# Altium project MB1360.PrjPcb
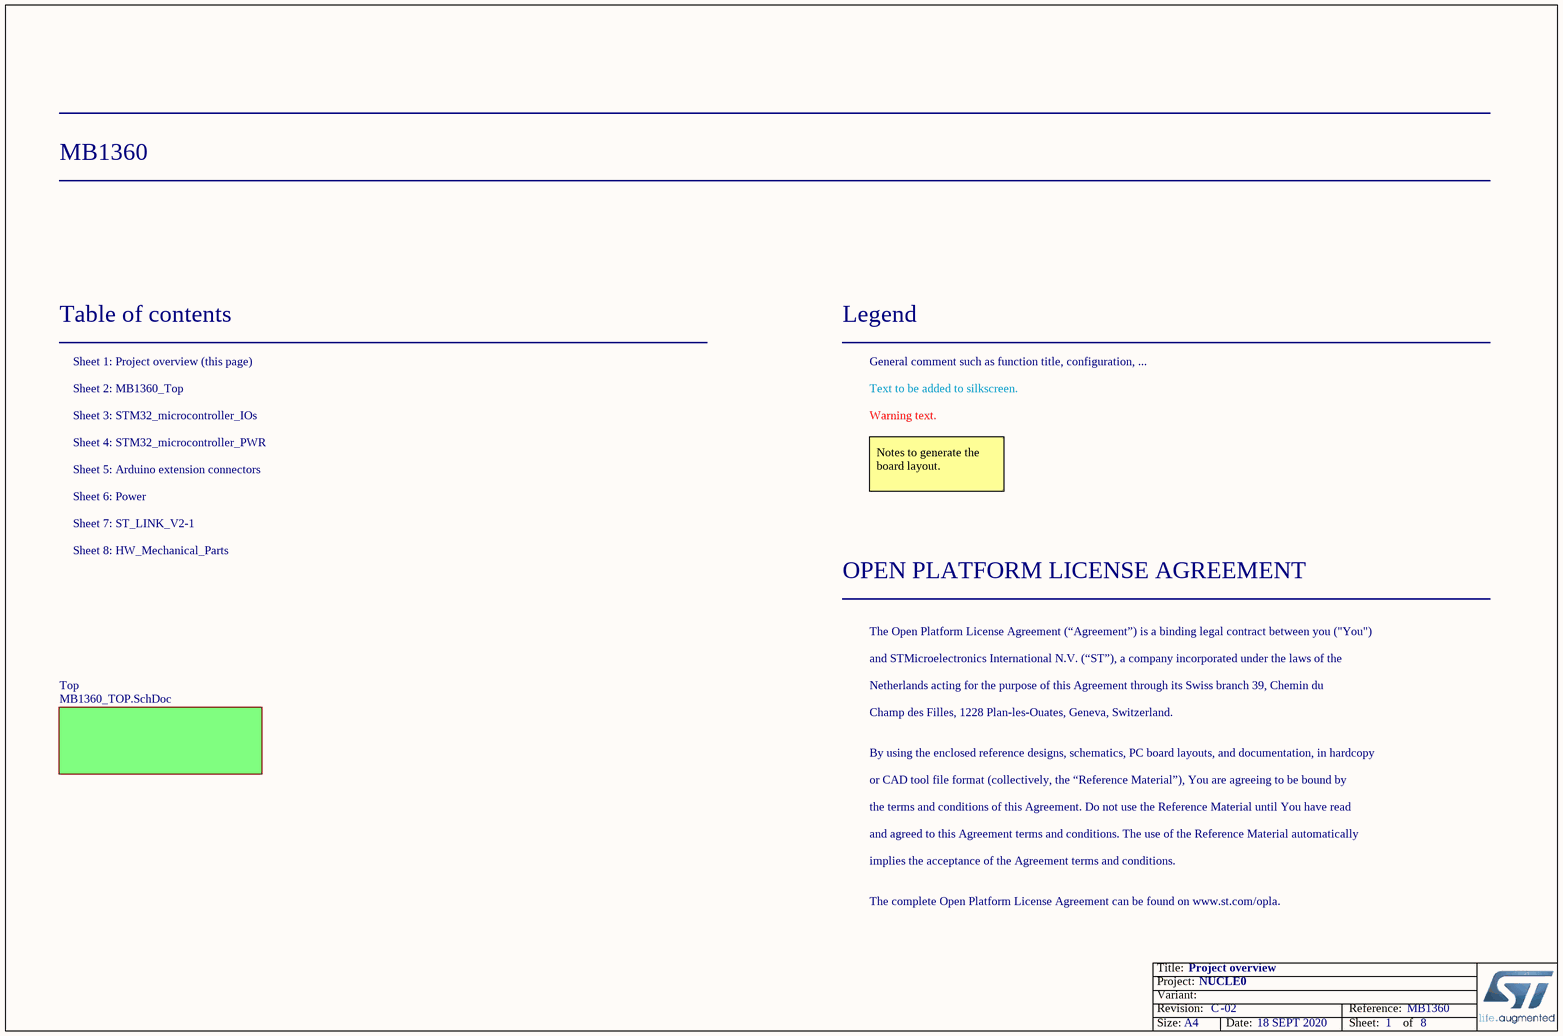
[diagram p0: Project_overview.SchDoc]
Board_Reference: MB1360; Board_PCB_Revision: C; Board_Name: NUCLE0; Board_Document_Date: 18 SEPT 2020; Board_Assembly_Revision: 02
8 sheets, 150 parts. Net scope: flat (ports and power ports of the same name join across sheets).
Board file: MB1360.PcbDoc
Sheets:
  Project_overview.SchDoc
    Top = MB1360_TOP.SchDoc
      ST_LINK_V2-1 = ST_LINK_V2-1.SchDoc
      Connectors = Arduino_extension_connectors.SchDoc
      MCU = STM32_microcontroller_IOs.SchDoc
      Power = Power.SchDoc
      STM32_microcontroller_power = STM32_microcontroller_power.SchDoc
      HW_Mechanical_Parts = HW_Mechanical_Parts.SchDoc

## Sheet Project_overview.SchDoc: Project overview
size A4; Date: Not used; ApprovedBy: Not used; CheckedBy: Not used; Author: Not used; CompanyName: STMicroelectronics; DrawnBy: Not used; Engineer: Not used; Organization: Not used; Address1: Not used; Address2: Not used; Address3: Not used; Address4: Not used; DocumentNumber: 1; Revision: Not used; SheetNumber: 1; SheetTotal: 8

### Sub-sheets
Top = MB1360_TOP.SchDoc: no entries

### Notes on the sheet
- Table of contents
- Sheet 1: Project overview (this page)
- Legend
- General comment such as function title, configuration, ...
- Sheet 2: MB1360_Top
- Sheet 4: STM32_microcontroller_PWR
- Sheet 3: STM32_microcontroller_IOs
- Text to be added to silkscreen.
- Warning text.
- Sheet 6: Power
- Sheet 5: Arduino extension connectors
- Notes to generate the board layout.
- Sheet 7: ST_LINK_V2-1
- Sheet 8: HW_Mechanical_Parts
- OPEN PLATFORM LICENSE AGREEMENT
- The Open Platform License Agreement (“Agreement”) is a binding legal contract between you ("You")
- and STMicroelectronics International N.V. (“ST”), a company incorporated under the laws of the
- Netherlands acting for the purpose of this Agreement through its Swiss branch 39, Chemin du
- Champ des Filles, 1228 Plan-les-Ouates, Geneva, Switzerland.
- By using the enclosed reference designs, schematics, PC board layouts, and documentation, in hardcopy
- or CAD tool file format (collectively, the “Reference Material”), You are agreeing to be bound by
- the terms and conditions of this Agreement. Do not use the Reference Material until You have read
- and agreed to this Agreement terms and conditions. The use of the Reference Material automatically
- implies the acceptance of the Agreement terms and conditions.
- The complete Open Platform License Agreement can be found on www.st.com/opla.

## Sheet MB1360_TOP.SchDoc: TOP
size A4; CompanyName: STMicroelectronics; Organization: Microcontrollers Division; SheetNumber: 2; SheetTotal: 8
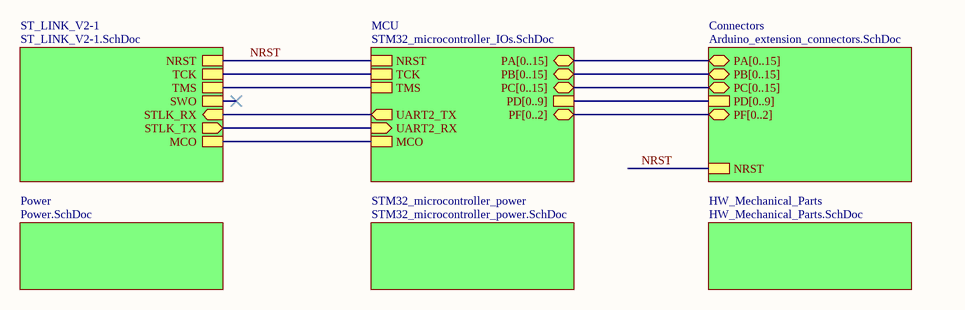
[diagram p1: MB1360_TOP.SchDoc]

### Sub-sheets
Connectors = Arduino_extension_connectors.SchDoc: PA[0..15] (bidir), PB[0..15] (bidir), PC[0..15] (bidir), NRST, PD[0..9], PF[0..2] (bidir)
HW_Mechanical_Parts = HW_Mechanical_Parts.SchDoc: no entries
MCU = STM32_microcontroller_IOs.SchDoc: NRST, MCO, UART2_RX (in), UART2_TX (out), PA[0..15] (bidir), PB[0..15] (bidir), PC[0..15] (bidir), TCK, TMS, PD[0..9], PF[0..2] (bidir)
Power = Power.SchDoc: no entries
ST_LINK_V2-1 = ST_LINK_V2-1.SchDoc: TMS, TCK, MCO, NRST, STLK_RX (in), STLK_TX (out), SWO
STM32_microcontroller_power = STM32_microcontroller_power.SchDoc: no entries

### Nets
NRST: sheet ST_LINK_V2-1/NRST, sheet Connectors/NRST, sheet MCU/NRST
(unnamed): sheet ST_LINK_V2-1/TMS, sheet MCU/TMS
(unnamed): sheet ST_LINK_V2-1/TCK, sheet MCU/TCK  [a separate net that carries the same name]
(unnamed): sheet ST_LINK_V2-1/MCO, sheet MCU/MCO  [a separate net that carries the same name]
(unnamed): sheet ST_LINK_V2-1/STLK_RX, sheet MCU/UART2_TX  [a separate net that carries the same name]
(unnamed): sheet ST_LINK_V2-1/STLK_TX, sheet MCU/UART2_RX  [a separate net that carries the same name]

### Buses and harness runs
bus sheet Connectors/PA[0..15] = sheet MCU/PA[0..15]
bus sheet Connectors/PB[0..15] = sheet MCU/PB[0..15]
bus sheet Connectors/PC[0..15] = sheet MCU/PC[0..15]
bus sheet Connectors/PD[0..9] = sheet MCU/PD[0..9]
bus sheet Connectors/PF[0..2] = sheet MCU/PF[0..2]

## Sheet ST_LINK_V2-1.SchDoc: ST_LINK_V2-1
size A4; CompanyName: STMicroelectronics; Organization: Microcontrollers Division; SheetNumber: 7; SheetTotal: 8
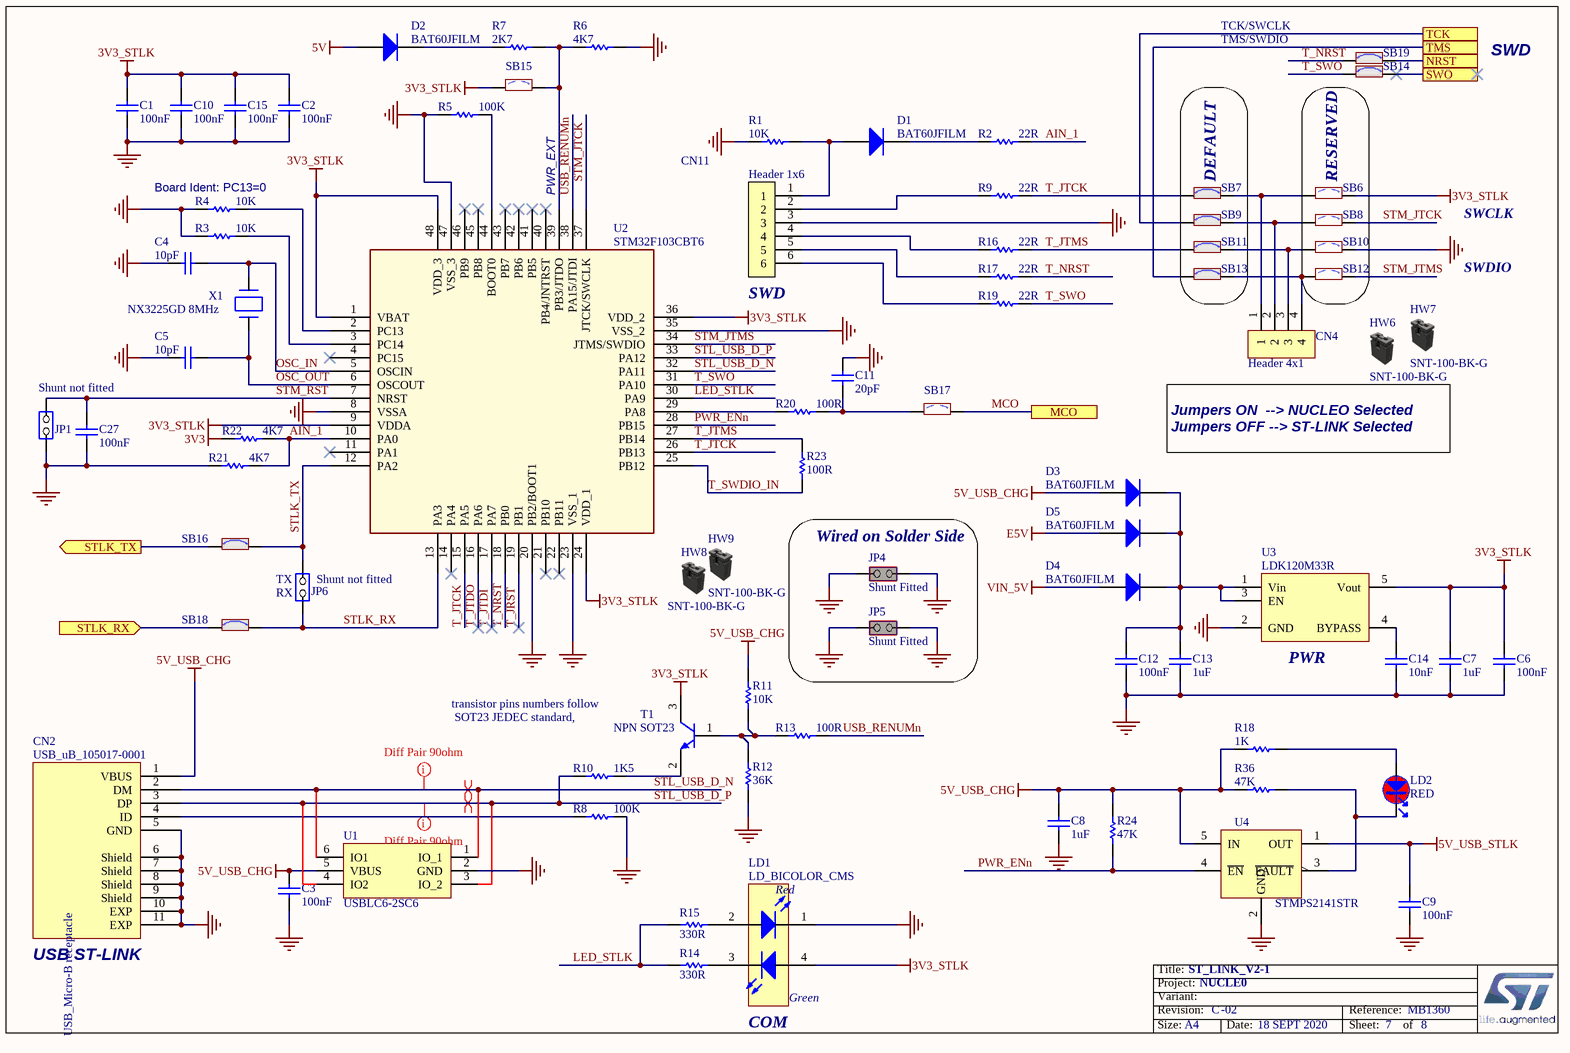
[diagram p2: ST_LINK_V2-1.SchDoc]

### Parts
C1  value 100nF  [C0603]  (hidden comment: Capacitor)
C2  value 100nF  [C0603]  (hidden comment: Capacitor)
C3  value 100nF  [C0603]  (hidden comment: Capacitor)
C4  value 10pF  [C0603]  (hidden comment: Capacitor)
C5  value 10pF  [C0603]  (hidden comment: Capacitor)
C6  value 100nF  [C0603]  (hidden comment: Capacitor)
C7  value 1uF  [C0603]  (hidden comment: Capacitor)
C8  value 1uF  [C0603]  (hidden comment: Capacitor)
C9  value 100nF  [C0603]  (hidden comment: Capacitor)
C10  value 100nF  [C0603]  (hidden comment: Capacitor)
C11  value 20pF  [C0603]  (hidden comment: Capacitor)
C12  value 100nF  [C0603]  (hidden comment: Capacitor)
C13  value 1uF  [C0603]  (hidden comment: Capacitor)
C14  value 10nF  [C0603]  (hidden comment: Capacitor)
C15  value 100nF  [C0603]  (hidden comment: Capacitor)
C27  value 100nF  [C0603]  (hidden comment: Capacitor)
CN2  value USB_uB_105017-0001  [CON_USBMICROB_MOLEX_105017-0001_H2P90]  (hidden comment: USB_uB_105017.0001)
CN4  Header 4x1  [CON_988-JIUBABA_PHFS25-11-04-G0B115-T-1]
CN11  value Header 1x6  [CON_988-JIUBABA_PHFS25-11-06-G0B115-T-1]  (hidden comment: Header 6x1)
D1  BAT60JFILM  [DIO_SOD323]
D2  BAT60JFILM  [DIO_SOD323]
D3  BAT60JFILM  [DIO_SOD323]
D4  BAT60JFILM  [DIO_SOD323]
D5  BAT60JFILM  [DIO_SOD323]
HW6  value SNT-100-BK-G  (hidden comment: Shunt Black 2.54mm)  (mechanical)
HW7  value SNT-100-BK-G  (hidden comment: Shunt Black 2.54mm)  (mechanical)
HW8  value SNT-100-BK-G  (hidden comment: Shunt Black 2.54mm)  (mechanical)
HW9  value SNT-100-BK-G  (hidden comment: Shunt Black 2.54mm)  (mechanical)
JP1  value Shunt not fitted  [CON_SAMTEC_TSW-102-07-G-S]  (hidden comment: Jumper_Header 2x1)
JP4  value Shunt Fitted  [CON_SAMTEC_TSW-102-07-G-S]  (hidden comment: Jumper_Header 2x1 Fitted)
JP5  value Shunt Fitted  [CON_SAMTEC_TSW-102-07-G-S]  (hidden comment: Jumper_Header 2x1 Fitted)
JP6  value Shunt not fitted  [CON_SAMTEC_TSW-102-07-G-S]  (hidden comment: Jumper_Header 2x1)
LD1  LD_BICOLOR_CMS  [LED_BI-GR_HSMF-A201-A00J1]
LD2  value RED  [LED_0603_RED]  (hidden comment: LED_red)
R1  value 10K  [R0603]  (hidden comment: Resistor)
R2  value 22R  [R0603]  (hidden comment: Resistor)
R3  value 10K  [R0603]  (hidden comment: Resistor)
R4  value 10K  [R0603]  (hidden comment: Resistor)
R5  value 100K  [R0603]  (hidden comment: Resistor)
R6  value 4K7  [R0603]  (hidden comment: Resistor)
R7  value 2K7  [R0603]  (hidden comment: Resistor)
R8  value 100K  [R0603]  (hidden comment: Resistor)
R9  value 22R  [R0603]  (hidden comment: Resistor)
R10  value 1K5  [R0603]  (hidden comment: Resistor)
R11  value 10K  [R0603]  (hidden comment: Resistor)
R12  value 36K  [R0603]  (hidden comment: Resistor)
R13  value 100R  [R0603]  (hidden comment: Resistor)
R14  value 330R  [R0603]  (hidden comment: Resistor)
R15  value 330R  [R0603]  (hidden comment: Resistor)
R16  value 22R  [R0603]  (hidden comment: Resistor)
R17  value 22R  [R0603]  (hidden comment: Resistor)
R18  value 1K  [R0603]  (hidden comment: Resistor)
R19  value 22R  [R0603]  (hidden comment: Resistor)
R20  value 100R  [R0603]  (hidden comment: Resistor)
R21  value 4K7  [R0603]  (hidden comment: Resistor)
R22  value 4K7  [R0603]  (hidden comment: Resistor)
R23  value 100R  [R0603]  (hidden comment: Resistor)
R24  value 47K  [R0603]  (hidden comment: Resistor)
R36  value 47K  [R0603]  (hidden comment: Resistor)
SB6  SB_OFF  [SOLDER-BRIDGE_R0603-0R]  (value not drawn)
SB7  SB_ON  [SOLDER-BRIDGE_R0603-0R]  (value not drawn)
SB8  SB_OFF  [SOLDER-BRIDGE_R0603-0R]  (value not drawn)
SB9  SB_ON  [SOLDER-BRIDGE_R0603-0R]  (value not drawn)
SB10  SB_OFF  [SOLDER-BRIDGE_R0603-0R]  (value not drawn)
SB11  SB_ON  [SOLDER-BRIDGE_R0603-0R]  (value not drawn)
SB12  SB_OFF  [SOLDER-BRIDGE_R0603-0R]  (value not drawn)
SB13  SB_ON  [SOLDER-BRIDGE_R0603-0R]  (value not drawn)
SB14  SB_ON  [SOLDER-BRIDGE_R0603-0R]  (value not drawn)
SB15  SB_OFF  [SOLDER-BRIDGE_R0603-0R]  (value not drawn)
SB16  SB_ON  [SOLDER-BRIDGE_R0603-0R]  (value not drawn)
SB17  SB_OFF  [SOLDER-BRIDGE_R0603-0R]  (value not drawn)
SB18  SB_ON  [SOLDER-BRIDGE_R0603-0R]  (value not drawn)
SB19  SB_ON  [SOLDER-BRIDGE_R0603-0R]  (value not drawn)
T1  value NPN SOT23  [NPN_SOT23]  (hidden comment: 9013-SOT23)
U1  USBLC6-2SC6  [ESD_SOT23-6L]
U2  STM32F103CBT6  [ICC_LQFP48_7X7_P050]
U3  LDK120M33R  [REG_SOT23-5L]
U4  STMPS2141STR  [MOS_SOT23-5L]
X1  value NX3225GD 8MHz  [CRY_NX3225GD_2P]  (hidden comment: XTAL_2_PINS)

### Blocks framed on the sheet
DEFAULT: SB7 SB9 SB11 SB13
RESERVED: SB6 SB8 SB10 SB12
Wired on Solder Side: JP4 JP5

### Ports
MCO, NRST, STLK_RX (in), STLK_TX (out), SWO, TCK, TMS

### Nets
3V3: R22.1
3V3_STLK: C1.2 C2.2 C6.2 C7.2 C10.2 C15.2 LD1.4(YellowGreen_anode) SB6.2 SB15.1 T1.3(C) U2.1(VBAT) U2.9(VDDA) U2.24(VDD_1) U2.36(VDD_2) U2.48(VDD_3) U3.5(Vout)
5V: D2.1(A)
5V_USB_CHG: C3.2 C8.1 CN2.1(VBUS) D3.1(A) R11.2 R18.2 R24.2 R36.2 U1.5(VBUS) U4.5(IN)
5V_USB_STLK: C9.2 U4.1(OUT)
E5V: D5.1(A)
GND: C1.1 C2.1 C3.1 C4.1 C5.1 C6.1 C7.1 C8.2 C9.1 C10.1 C11.2 C12.1 C13.1 C14.1 C15.1 C27.2 CN2.5(GND) CN2.6(Shield) CN2.7(Shield) CN2.8(Shield) CN2.9(Shield) CN2.10(EXP) CN2.11(EXP) CN11.3 JP1.2(NO) JP4.1(COMMON) JP4.2(NO) JP5.1(COMMON) JP5.2(NO) LD1.1(RED_cathode) R1.2 R3.1 R4.1 R5.1 R6.2 R8.2 R12.1 R21.1 SB10.2 U1.2(GND) U2.8(VSSA) U2.20(PB2/BOOT1) U2.23(VSS_1) U2.35(VSS_2) U2.47(VSS_3) U3.2(GND) U4.2(GND)
VIN_5V: D4.1(A)
AIN_1: R2.2 R21.2 R22.2 U2.10(PA0)
LED_STLK: R14.1 R15.1 U2.30(PA9)
MCO: SB17.2 ; port MCO
NRST: SB19.2 ; port NRST
OSC_IN: C4.2 U2.5(OSCIN) X1.2(X2)
OSC_OUT: C5.2 U2.6(OSCOUT) X1.1(X1)
PA13: SB13.1 ; port TMS
PA14: SB9.1 ; port TCK
PWR_ENn: R24.1 U2.28(PB15) U4.4(~{EN})
STL_USB_D_N: CN2.2(DM) U1.1(IO_1) U1.6(IO1) U2.32(PA11)
STL_USB_D_P: CN2.3(DP) R10.1 U1.3(IO_2) U1.4(IO2) U2.33(PA12)
STLK_RX: JP6.1(COMMON) SB18.2 U2.13(PA3)
STLK_TX: JP6.2(NO) SB16.2 U2.12(PA2)
STM_JTCK: SB8.2 U2.37(JTCK/SWCLK)
STM_JTMS: SB12.2 U2.34(JTMS/SWDIO)
STM_RST: C27.1 JP1.1(COMMON) U2.7(NRST)
T_JRST: U2.19(PB1)
T_JTCK: R9.2 SB7.1 U2.15(PA5) U2.26(PB13)
T_JTDI: U2.17(PA7)
T_JTDO: U2.16(PA6)
T_JTMS: R16.2 R23.2 SB11.1 U2.27(PB14)
T_NRST: R17.2 SB19.1 U2.18(PB0)
T_SWDIO_IN: R23.1 U2.25(PB12)
T_SWO: R19.2 SB14.1 U2.31(PA10)
USB_RENUMn: R13.2 U2.38(PA15/JTDI)
NetC11_1: C11.1 R20.2 SB17.1
NetC12_2: C12.2 C13.2 D3.2(K) D4.2(K) D5.2(K) U3.1(Vin) U3.3(EN)
NetC14_2: C14.2 U3.4(BYPASS)
NetCN2_4: CN2.4(ID) R8.1
NetCN4_1: CN4.1 SB6.1 SB7.2
NetCN4_2: CN4.2 SB8.1 SB9.2
NetCN4_3: CN4.3 SB10.1 SB11.2
NetCN4_4: CN4.4 SB12.1 SB13.2
NetCN11_1: CN11.1 D1.1(A) R1.1
NetCN11_2: CN11.2 R9.1
NetCN11_4: CN11.4 R16.1
NetCN11_5: CN11.5 R17.1
NetCN11_6: CN11.6 R19.1
NetD1_2: D1.2(K) R2.1
NetD2_2: D2.2(K) R7.1
NetLD1_2: LD1.2(Red_anode) R15.2
NetLD1_3: LD1.3(YellowGreen_cathode) R14.2
NetLD2_1: LD2.1 R18.1
NetLD2_2: LD2.2 R36.1 U4.3(~{FAULT})
NetR3_2: R3.2 U2.3(PC14)
NetR4_2: R4.2 U2.2(PC13)
NetR5_2: R5.2 U2.44(BOOT0)
NetR6_1: R6.1 R7.2 SB15.2 U2.39(PB3/JTDO)
NetR10_2: R10.2 T1.2(E)
NetR11_1: R11.1 R12.2 R13.1 T1.1(B)
NetR20_1: R20.1 U2.29(PA8)
NetSB14_2: SB14.2 ; port SWO
NetSB16_1: SB16.1 ; port STLK_TX
NetSB18_1: SB18.1 ; port STLK_RX

Not connected (* = marked no-connect by the designer): U2 4(PC15)* 11(PA1)* 14(PA4)* 21(PB10)* 22(PB11)* 40(PB4/JNTRST)* 41(PB5)* 42(PB6)* 43(PB7)* 45(PB8)* 46(PB9)*

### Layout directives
mark named Diff Pair 90ohm: STL_USB_D_N, STL_USB_D_P
differential pair: STL_USB_D_N, STL_USB_D_P

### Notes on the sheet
- TCK/SWCLK
- TMS/SWDIO
- SWD
- (near R4) Board Ident: PC13=0
- PWR_EXT
- SWCLK
- (near CN11) SWD
- SWDIO
- Jumpers ON  --> NUCLEO Selected
  Jumpers OFF --> ST-LINK Selected
- (near JP6) TX
- (near JP6) RX
- (near U3) PWR
- (near T1) transistor pins numbers follow
  SOT23 JEDEC standard,
- (near CN2) USB ST-LINK
- COM

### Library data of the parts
C1-C3 C6 C9 C10 C12 C15 C27 = MCD-00211: Capacitor, MLCC, 100nF, 16V, X7R, 10%, 0603, T=0,8mm; Manufacturer_Part_Number: CC0603KRX7R7BB104; Manufacturer: YAGEO; ECCN_US: EAR99; ECCN_EU: NEC; Provided_By: SUBCO
C4 C5 = MCD-00637: Capacitor, MLCC, 10pF, 50V, NPO, 5%, 0603, T=0,8mm; Manufacturer_Part_Number: CC0603JRNPO9BN100; Manufacturer: YAGEO; ECCN_US: EAR99; ECCN_EU: NEC; Provided_By: SUBCO
C7 C13 = MCD-00010: Capacitor, MLCC, 1uF, 16V, X5R, 10%, 0603, T=0,8mm; Manufacturer_Part_Number: CC0603KRX5R7BB105; Manufacturer: YAGEO; ECCN_US: EAR99; ECCN_EU: NEC; Provided_By: SUBCO
C8 = MCD-00238: Capacitor, MLCC, 1uF, 6V3, X5R, 10%, 0603, T=0,8mm; Manufacturer_Part_Number: CC0603KRX5R5BB105; Manufacturer: YAGEO; ECCN_US: EAR99; ECCN_EU: NEC; Provided_By: SUBCO
C11 = MCD-00638: Capacitor, MLCC, 20pF, 50V, NPO, 5%, 0603, T=0,8mm; Manufacturer_Part_Number: CC0603JRNPO9BN200; Manufacturer: YAGEO; ECCN_US: EAR99; ECCN_EU: NEC; Provided_By: SUBCO
C14 = MCD-00017: Capacitor, MLCC, 10nF, 50V, X7R, 10%, 0603, T=0.8mm; Manufacturer_Part_Number: CC0603KRX7R9BB103; Manufacturer: YAGEO; ECCN_US: EAR99; ECCN_EU: NEC; Provided_By: SUBCO
CN2 = MCD-00028: USB-MICRO-B, 0.65mm, RA, SMT, Bottom Mount,; Part_Type: Connector; Manufacturer_Part_Number: 1050170001; Manufacturer: MOLEX; Provided_By: SUBCO
CN4 = MCD-00313: Header, 4x1, 2.54mm, VR, TH, Height 6mm/3mm; Part_Type: Connector; Manufacturer_Part_Number: PHFS25-11-04-G0B115-T-1; Manufacturer: JIUBABA; Alternate_Manufacturer_Part_Number: 313104S1411160; Alternate_Manufacturer: LIANYI; Provided_By: SUBCO
CN11 = MCD-00316: Header, 6x1, 2.54mm, VR, TH, Height 6mm/3mm; Part_Type: Connector; Manufacturer_Part_Number: PHFS25-11-06-G0B115-T-1; Manufacturer: JIUBABA; Alternate_Manufacturer_Part_Number: 313106S1411160; Alternate_Manufacturer: LIANYI; Provided_By: SUBCO
D1 D3-D5 = MCD-00034: Part_Type: Diode; Manufacturer: STMICROELECTRONICS; BMS_Part_Number: 9151097; ECCN_US: EAR99; ECCN_EU: NEC; Provided_By: SUBCO with ST control
D2 = MCD-00034: Manufacturer: STMICROELECTRONICS; Part_Type: Diode; BMS_Part_Number: 9151097; ECCN_US: EAR99; ECCN_EU: NEC; Provided_By: SUBCO with ST control
HW6-HW9 = MCD-00043: SHUNT 2.54mm BLACK; Manufacturer: SAMTEC; Part_Type: Mechanical; Alternate_Manufacturer_Part_Number: 316102S111A; Alternate_Manufacturer: JIUBABA; Provided_By: SUBCO
JP1 JP6 = MCD-00045: Header, 2x1, 2,54mm, VR, TH, Height 5.84mm/2.54mm; Part_Type: Connector; Manufacturer_Part_Number: TSW-102-07-G-S; Manufacturer: SAMTEC; Alternate_Manufacturer_Part_Number: 313102S111116;313102S111116; Alternate_Manufacturer: JIUBABA; LIANYI; Provided_By: SUBCO
JP4 JP5 = MCD-00683: Header, 2x1, 2,54mm, VR, TH, Height 5.84mm/2.54mm - Shunt Fitted by default; Part_Type: Connector; Manufacturer_Part_Number: TSW-102-07-x-S; Manufacturer: SAMTEC; Alternate_Manufacturer_Part_Number: 313102S111116; Alternate_Manufacturer: LIANYI; Provided_By: SUBCO
LD1 = MCD-00051: LED Bicolor; Part_Type: Display; Manufacturer_Part_Number: HSMF-A201-A00J1; Manufacturer: AVAGO TECHNOLOGIES; Alternate_Manufacturer_Part_Number: LE-RGW35280; Alternate_Manufacturer: EVERLUCK; ECCN_US: EAR99; ECCN_EU: NEC; Provided_By: SUBCO
LD2 = MCD-00049: LED, Red, 0603; Manufacturer_Part_Number: 19-213-R6C-AP1Q2B/3T; Manufacturer: EVERLIGHT; Part_Type: Display; ECCN_US: EAR99; ECCN_EU: NEC; Provided_By: SUBCO
R1 R3 R4 R11 = MCD-00220: Resistor,10K,0603,1%,1/10W; Manufacturer_Part_Number: RC0603FR-0710KL; Manufacturer: YAGEO; ECCN_US: EAR99; ECCN_EU: NEC; Provided_By: SUBCO
R2 R9 R16 R17 R19 = MCD-00066: Resistor,22R,0603,1%,1/10W; Manufacturer_Part_Number: RC0603FR-0722RL; Manufacturer: YAGEO; ECCN_US: EAR99; ECCN_EU: NEC; Provided_By: SUBCO
R5 R8 = MCD-00223: Resistor,100K,0603,1%,1/10W; Manufacturer_Part_Number: RC0603FR-07100KL; Manufacturer: YAGEO; ECCN_US: EAR99; ECCN_EU: NEC; Provided_By: SUBCO
R6 R21 R22 = MCD-00219: Resistor,4K7,0603,1%,1/10W; Manufacturer_Part_Number: RC0603FR-074K7L; Manufacturer: YAGEO; ECCN_US: EAR99; ECCN_EU: NEC; Provided_By: SUBCO
R7 = MCD-00218: Resistor,2K7,0603,1%,1/10W; Manufacturer_Part_Number: RC0603FR-072K7L; Manufacturer: YAGEO; BMS_Part_Number: 9129767; ECCN_US: EAR99; ECCN_EU: NEC; Provided_By: SUBCO
R10 = MCD-00217: Resistor,1K5,0603,1%,1/10W; Manufacturer_Part_Number: RC0603FR-071K5L; Manufacturer: YAGEO; BMS_Part_Number: 9129766; ECCN_US: EAR99; ECCN_EU: NEC; Provided_By: SUBCO
R12 = MCD-00221: Resistor,36K,0603,1%,1/10W; Manufacturer_Part_Number: RC0603FR-0736KL; Manufacturer: YAGEO; ECCN_US: EAR99; ECCN_EU: NEC; Provided_By: SUBCO
R13 R20 R23 = MCD-00224: Resistor,100R,0603,1%,1/10W; Manufacturer_Part_Number: RC0603FR-07100RL; Manufacturer: YAGEO; ECCN_US: EAR99; ECCN_EU: NEC; Provided_By: SUBCO
R14 R15 = MCD-00197: Resistor,330R,0603,1%,1/10W; Manufacturer_Part_Number: RC0603FR-07330RL; Manufacturer: YAGEO; BMS_Part_Number: 9129729; ECCN_US: EAR99; ECCN_EU: NEC; Provided_By: SUBCO
R18 = MCD-00070: Resistor,1K,0603,1%,1/10W; Manufacturer_Part_Number: RC0603FR-071KL; Manufacturer: YAGEO; ECCN_US: EAR99; ECCN_EU: NEC; Provided_By: SUBCO
R24 R36 = MCD-00222: Resistor,47K,0603,1%,1/10W; Manufacturer_Part_Number: RC0603FR-0747KL; Manufacturer: YAGEO; ECCN_US: EAR99; ECCN_EU: NEC; Provided_By: SUBCO
SB6 SB8 SB10 SB12 SB15 SB17 = MCD-00072: Solder Bridge OFF; Part_Type: Mechanical; Manufacturer_Part_Number: RC0603JR-070RL; Manufacturer: YAGEO; Provided_By: SUBCO
SB7 SB9 SB11 SB13 SB14 SB16 SB18 SB19 = MCD-00071: Solder Bridge ON; Part_Type: Mechanical; Manufacturer_Part_Number: RC0603JR-070RL; Manufacturer: YAGEO; Provided_By: SUBCO
T1 = MCD-00073: NPN Bipolar Transistor; Part_Type: IC; Manufacturer_Part_Number: BSR14; Manufacturer: ON SEMICONDUCTOR; Alternate_Manufacturer_Part_Number: MMBT2222LT1G / MMBT2222ALT1G / MMBT2222ALT3G; ECCN_US: EAR99; ECCN_EU: NEC; Provided_By: SUBCO
U1 = MCD-00163: Very low capacitance ESD protection; Part_Type: IC; Manufacturer: STMICROELECTRONICS; BMS_Part_Number: 9151075; ECCN_US: EAR99; ECCN_EU: NEC; Provided_By: SUBCO with ST control
U2 = MCD-00085: Medium-density performance line ARM-based 32-bit MCU with 128KB Flash; Manufacturer: STMICROELECTRONICS; Part_Type: IC; BMS_Part_Number: 9175111; ECCN_US: 3A991A2; ECCN_EU: NEC; Provided_By: SUBCO with ST control
U3 = MCD-00663: 200 mA low quiescent current very low noise LDO; Part_Type: IC; Manufacturer: STMICROELECTRONICS; BMS_Part_Number: 9176330; ECCN_US: EAR99; ECCN_EU: NEC; Provided_By: SUBCO with ST control
U4 = MCD-00083: Enhanced single channel power switches with active low enable pin; Part_Type: IC; Manufacturer: STMICROELECTRONICS; Alternate_Manufacturer_Part_Number: TPS2041C; Alternate_Manufacturer: TEXAS INSTRUMENTS; BMS_Part_Number: 9159003; ECCN_US: EAR99; ECCN_EU: NEC; Provided_By: SUBCO with ST control
X1 = MCD-00092: Crystal 8MHz, 8pF, +-20ppm, 500ohms max,  SMD; Part_Type: Crystal_Osc; Manufacturer_Part_Number: NX3225GD 8MHz EXS00A-CG04874; Manufacturer: NDK; BMS_Part_Number: 9157029; ECCN_US: EAR99; ECCN_EU: NEC; Provided_By: SUBCO

## Sheet Arduino_extension_connectors.SchDoc: Connectors
size A4; CompanyName: STMicroelectronics; Organization: Microcontrollers Division; SheetNumber: 5; SheetTotal: 8
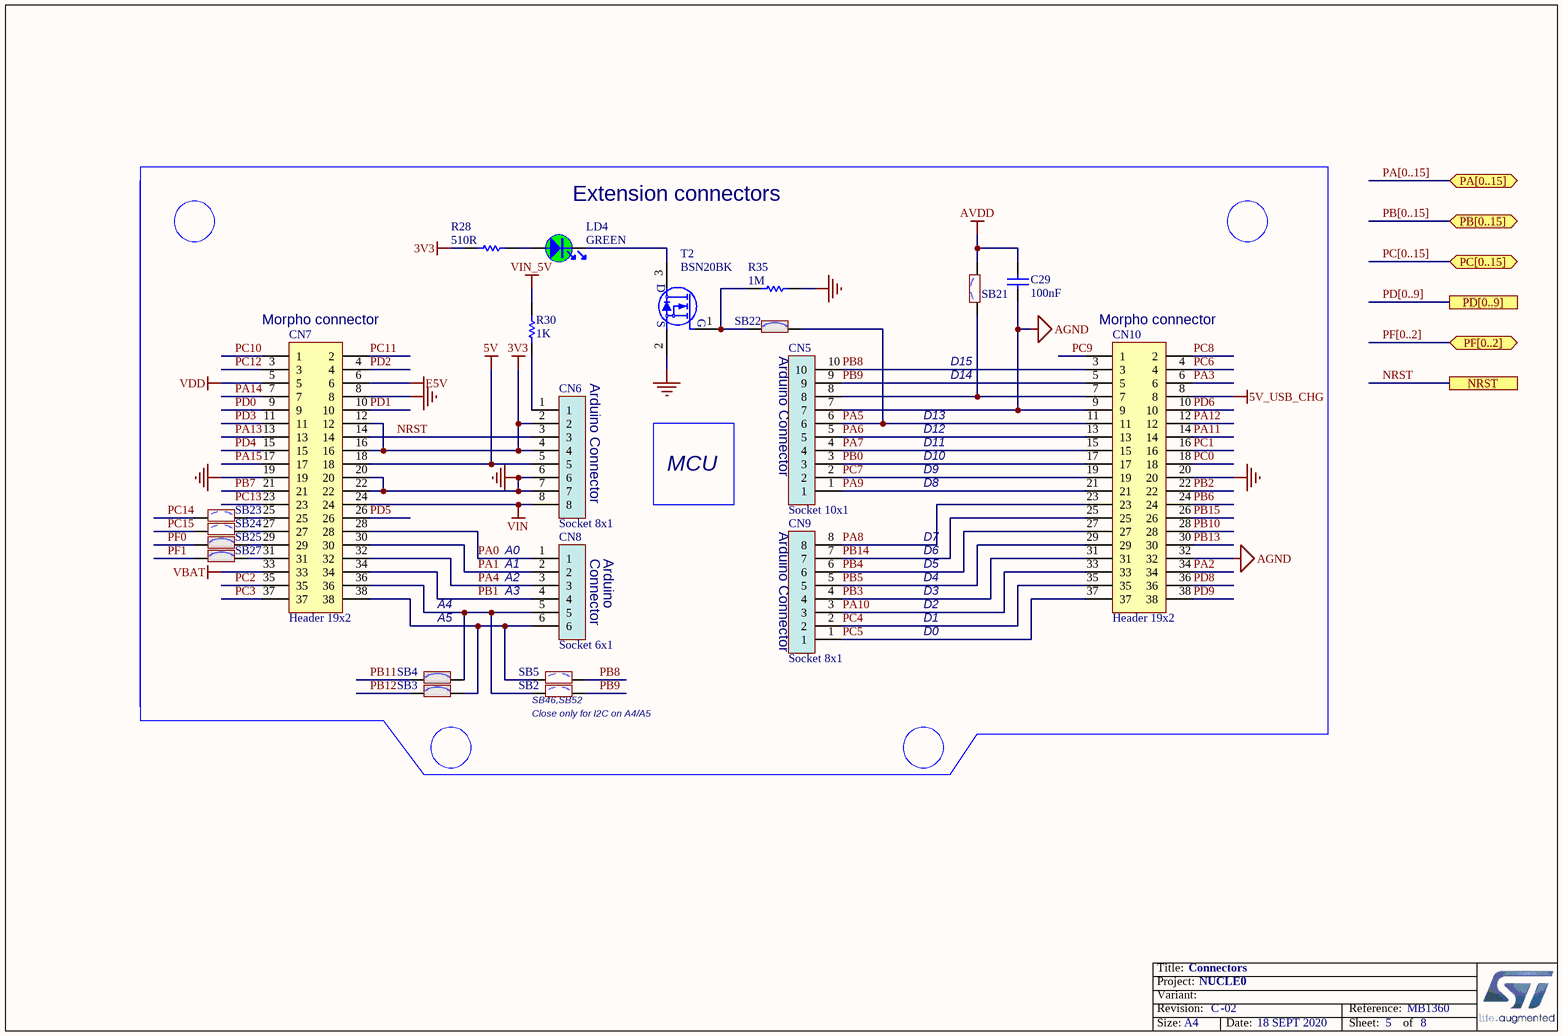
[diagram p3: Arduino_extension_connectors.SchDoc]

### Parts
C29  value 100nF  [C0603]  (hidden comment: Capacitor)
CN5  Socket 10x1  [CON_SAMTEC_SSW-110-03-X-S]
CN6  Socket 8x1  [CON_SAMTEC_SSW-108-03-X-S]
CN7  Header 19x2  [CON_SAMTEC_TSW-119-09-X-D]
CN8  Socket 6x1  [CON_SAMTEC_SSW-106-03-X-S]
CN9  Socket 8x1  [CON_SAMTEC_SSW-108-03-X-S]
CN10  Header 19x2  [CON_SAMTEC_TSW-119-09-X-D]
LD4  value GREEN  [LED_0603_GREEN]  (hidden comment: LED_green)
R28  value 510R  [R0603]  (hidden comment: Resistor)
R30  value 1K  [R0603]  (hidden comment: Resistor)
R35  value 1M  [R0603]  (hidden comment: Resistor)
SB2  SB_OFF  [SOLDER-BRIDGE_R0603-0R]  (value not drawn)
SB3  SB_ON  [SOLDER-BRIDGE_R0603-0R]  (value not drawn)
SB4  SB_ON  [SOLDER-BRIDGE_R0603-0R]  (value not drawn)
SB5  SB_OFF  [SOLDER-BRIDGE_R0603-0R]  (value not drawn)
SB21  SB_OFF  [SOLDER-BRIDGE_R0603-0R]  (value not drawn)
SB22  SB_ON  [SOLDER-BRIDGE_R0603-0R]  (value not drawn)
SB23  SB_OFF  [SOLDER-BRIDGE_R0603-0R]  (value not drawn)
SB24  SB_OFF  [SOLDER-BRIDGE_R0603-0R]  (value not drawn)
SB25  SB_ON  [SOLDER-BRIDGE_R0603-0R]  (value not drawn)
SB27  SB_ON  [SOLDER-BRIDGE_R0603-0R]  (value not drawn)
T2  value BSN20BK  [MOS_SOT23]  (hidden comment: BSN20)

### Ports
NRST, PA[0..15] (bidir), PB[0..15] (bidir), PC[0..15] (bidir), PD[0..9], PF[0..2] (bidir)

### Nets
3V3: CN6.2 CN6.4 CN7.12 CN7.16 R28.2
5V: CN6.5 CN7.18
5V_USB_CHG: CN10.8
AGND: C29.1 CN5.7 CN10.9 CN10.32
AVDD: C29.2 SB21.2
E5V: CN7.6
GND: CN6.6 CN6.7 CN7.8 CN7.19 CN7.20 CN7.22 CN10.20 R35.2 T2.2(S)
VBAT: CN7.33
VDD: CN7.5
VIN: CN6.8 CN7.24
VIN_5V: R30.1
NRST: CN6.3 CN7.14 ; port NRST
PA0: CN7.28 CN8.1
PA1: CN7.30 CN8.2
PA2: CN10.34
PA3: CN10.6
PA4: CN7.32 CN8.3
PA5: CN5.6 CN10.11 SB22.2
PA6: CN5.5 CN10.13
PA7: CN5.4 CN10.15
PA8: CN9.8 CN10.23
PA9: CN5.1 CN10.21
PA10: CN9.3 CN10.33
PA11: CN10.14
PA12: CN10.12
PA13: CN7.13
PA14: CN7.7
PA15: CN7.17
PB0: CN5.3 CN10.17
PB1: CN7.34 CN8.4
PB2: CN10.22
PB3: CN9.4 CN10.31
PB4: CN9.6 CN10.27
PB5: CN9.5 CN10.29
PB6: CN10.24
PB7: CN7.21
PB8: CN5.10 CN10.3 SB5.2
PB9: CN5.9 CN10.5 SB2.2
PB10: CN10.28
PB11: SB4.1
PB12: SB3.1
PB13: CN10.30
PB14: CN9.7 CN10.25
PB15: CN10.26
PC0: CN10.18
PC1: CN10.16
PC2: CN7.35
PC3: CN7.37
PC4: CN9.2 CN10.35
PC5: CN9.1 CN10.37
PC6: CN10.4
PC7: CN5.2 CN10.19
PC8: CN10.2
PC9: CN10.1
PC10: CN7.1
PC11: CN7.2
PC12: CN7.3
PC13: CN7.23
PC14: SB23.1
PC15: SB24.1
PD0: CN7.9
PD1: CN7.10
PD2: CN7.4
PD3: CN7.11
PD4: CN7.15
PD5: CN7.26
PD6: CN10.10
PD8: CN10.36
PD9: CN10.38
PF0: SB25.1  [project net MCO]
PF1: SB27.1
NetCN5_8: CN5.8 CN10.7 SB21.1
NetCN6_1: CN6.1 R30.2
NetCN7_25: CN7.25 SB23.2
NetCN7_27: CN7.27 SB24.2
NetCN7_29: CN7.29 SB25.2
NetCN7_31: CN7.31 SB27.2
NetCN7_36: CN7.36 CN8.5 SB2.1 SB4.2
NetCN7_38: CN7.38 CN8.6 SB3.2 SB5.1
NetLD4_1: LD4.1 R28.1
NetLD4_2: LD4.2 T2.3(D)
NetR35_1: R35.1 SB22.1 T2.1(G)

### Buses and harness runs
bus PA[0..15] = port PA[0..15]
bus PB[0..15] = port PB[0..15]
bus PC[0..15] = port PC[0..15]
bus PD[0..9] = port PD[0..9]
bus PF[0..2] = port PF[0..2]

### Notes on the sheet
- (near LD4) Extension connectors
- (near CN7) Morpho connector
- (near CN6) Arduino Connector
- Arduino Connector
- D14
- D15
- (near CN10) Morpho connector
- D13
- D12
- D11
- MCU
- D8
- D9
- D10
- A0
- (near CN8) A1
- (near CN8) A2
- (near CN8) Connector
- (near CN8) Arduino
- (near CN9) Arduino Connector
- D4
- D5
- D6
- D7
- A4
- A5
- (near CN8) A3
- D0
- D1
- D2
- D3
- (near SB2) Close only for I2C on A4/A5
- (near SB2) SB46,SB52

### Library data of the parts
C29 = MCD-00211: as C1 on sheet ST_LINK_V2-1
CN5 = MCD-00262: Socket, 10x1, 2.54mm, VR, TH, Height 8.51mm/10mm; Manufacturer_Part_Number: SSW-110-03-x-S; Manufacturer: SAMTEC; Part_Type: Connector; Provided_By: SUBCO
CN6 = MCD-00261: Socket, 8x1, 2.54mm, VR, TH, Height 8.51mm/10mm; Manufacturer_Part_Number: SSW-108-03-x-S; Manufacturer: SAMTEC; Part_Type: Connector; Provided_By: SUBCO
CN7 CN10 = MCD-00213: Header, 19x2, 2,54mm, VR, TH, Height 5.84mm/10.16mm; Manufacturer_Part_Number: TSW-119-09-x-D; Manufacturer: SAMTEC; Part_Type: Connector; Provided_By: SUBCO
CN8 = MCD-00260: Socket, 6x1, 2.54mm, VR, TH, Height 8.51mm/10mm; Part_Type: Connector; Manufacturer_Part_Number: SSW-106-03-x-S; Manufacturer: SAMTEC; Provided_By: SUBCO
CN9 = MCD-00261: Socket, 8x1, 2.54mm, VR, TH, Height 8.51mm/10mm; Part_Type: Connector; Manufacturer_Part_Number: SSW-108-03-x-S; Manufacturer: SAMTEC; Provided_By: SUBCO
LD4 = MCD-00050: LED, Green, 0603; Part_Type: Display; Manufacturer_Part_Number: 19-213SYGC/S530-E2/TR8; Manufacturer: EVERLIGHT; ECCN_US: EAR99; ECCN_EU: NEC; Provided_By: SUBCO
R28 = MCD-00225: Resistor,510R,0603,1%,1/10W; Manufacturer_Part_Number: RC0603FR-07510RL; Manufacturer: YAGEO; ECCN_US: EAR99; ECCN_EU: NEC; Provided_By: SUBCO
R30 = MCD-00070: as R18 on sheet ST_LINK_V2-1
R35 = MCD-00257: Resistor,1M,0603,1%,1/10W; Manufacturer_Part_Number: RC0603FR-071ML; Manufacturer: YAGEO; ECCN_US: EAR99; ECCN_EU: NEC; Provided_By: SUBCO
SB2 SB5 SB21 SB23 SB24 = MCD-00072: as SB6 on sheet ST_LINK_V2-1
SB3 SB4 SB22 SB25 SB27 = MCD-00071: as SB7 on sheet ST_LINK_V2-1
T2 = MCD-01969: N-channel enhancement mode field-effect transistor; Manufacturer: NEXPERIA; ECCN_US: EAR99; ECCN_EU: NEC; Provided_By: SUBCO

## Sheet STM32_microcontroller_IOs.SchDoc: STM32_microcontroller_IOs
size A4; CompanyName: STMicroelectronics; Organization: Microcontrollers Division; SheetNumber: 3; SheetTotal: 8
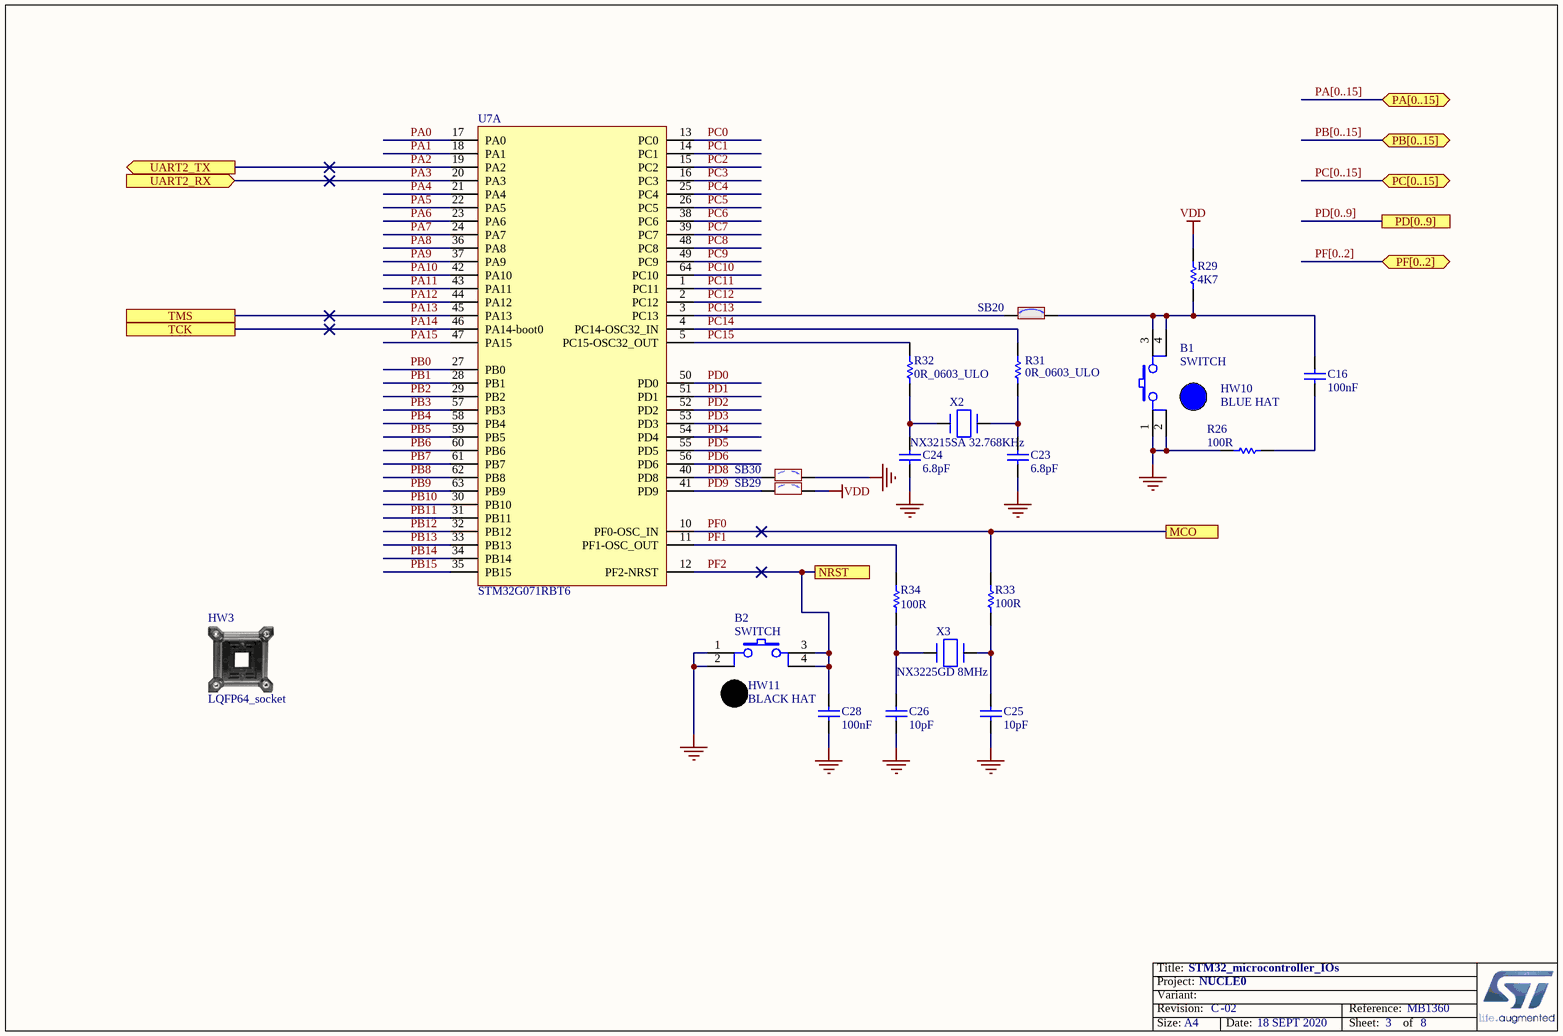
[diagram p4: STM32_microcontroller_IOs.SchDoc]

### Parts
B1  value SWITCH  [SWI_WEALTHMETAL_TD-0341_4P_BLUE]  (hidden comment: SW-PUSH-CMS)
B2  value SWITCH  [SWI_WEALTHMETAL_TD-0341_4P_BLACK]  (hidden comment: SW-PUSH-CMS)
C16  value 100nF  [C0603]  (hidden comment: Capacitor)
C23  value 6.8pF  [C0603]  (hidden comment: Capacitor)
C24  value 6.8pF  [C0603]  (hidden comment: Capacitor)
C25  value 10pF  [C0603]  (hidden comment: Capacitor)
C26  value 10pF  [C0603]  (hidden comment: Capacitor)
C28  value 100nF  [C0603]  (hidden comment: Capacitor)
HW3  value LQFP64_socket  (hidden comment: SOCKET_LQFP64)  (mechanical)
HW10  value BLUE HAT  (hidden comment: BUTTON_HAT_BLUE)  (mechanical)
HW11  value BLACK HAT  (hidden comment: BUTTON_HAT_BLACK)  (mechanical)
R26  value 100R  [R0603]  (hidden comment: Resistor)
R29  value 4K7  [R0603]  (hidden comment: Resistor)
R31  value 0R_0603_ULO  [R0603]  (hidden comment: Resistor)
R32  value 0R_0603_ULO  [R0603]  (hidden comment: Resistor)
R33  value 100R  [R0603]  (hidden comment: Resistor)
R34  value 100R  [R0603]  (hidden comment: Resistor)
SB20  SB_ON  [SOLDER-BRIDGE_R0603-0R]  (value not drawn)
SB29  SB_OFF  [SOLDER-BRIDGE_R0603-0R]  (value not drawn)
SB30  SB_OFF  [SOLDER-BRIDGE_R0603-0R]  (value not drawn)
U7  STM32G071RBT6  [ICC_LQFP64_10X10_P050_SOCKET_YAMAICHI_IC149-064-069-B5]  (part A of 2)
X2  value NX3215SA 32.768KHz  [CRY_NX3215SA_2P]  (hidden comment: XTAL_2_PINS)
X3  value NX3225GD 8MHz  [CRY_NX3225GD_2P]  (hidden comment: XTAL_2_PINS)

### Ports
MCO, NRST, PA[0..15] (bidir), PB[0..15] (bidir), PC[0..15] (bidir), PD[0..9], PF[0..2] (bidir), TCK, TMS, UART2_RX (in), UART2_TX (out)

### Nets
GND: B1.1 B1.2 B2.1 B2.2 C23.1 C24.1 C25.1 C26.1 C28.1 R26.1 SB30.2
VDD: R29.2 SB29.2
PA0: U7.17(PA0)
PA1: U7.18(PA1)
PA2: U7.19(PA2) ; port UART2_TX
PA3: U7.20(PA3) ; port UART2_RX
PA4: U7.21(PA4)
PA5: U7.22(PA5)
PA6: U7.23(PA6)
PA7: U7.24(PA7)
PA8: U7.36(PA8)
PA9: U7.37(PA9)
PA10: U7.42(PA10)
PA11: U7.43(PA11)
PA12: U7.44(PA12)
PA13: U7.45(PA13) ; port TMS
PA14: U7.46(PA14-boot0) ; port TCK
PA15: U7.47(PA15)
PB0: U7.27(PB0)
PB1: U7.28(PB1)
PB2: U7.29(PB2)
PB3: U7.57(PB3)
PB4: U7.58(PB4)
PB5: U7.59(PB5)
PB6: U7.60(PB6)
PB7: U7.61(PB7)
PB8: U7.62(PB8)
PB9: U7.63(PB9)
PB10: U7.30(PB10)
PB11: U7.31(PB11)
PB12: U7.32(PB12)
PB13: U7.33(PB13)
PB14: U7.34(PB14)
PB15: U7.35(PB15)
PC0: U7.13(PC0)
PC1: U7.14(PC1)
PC2: U7.15(PC2)
PC3: U7.16(PC3)
PC4: U7.25(PC4)
PC5: U7.26(PC5)
PC6: U7.38(PC6)
PC7: U7.39(PC7)
PC8: U7.48(PC8)
PC9: U7.49(PC9)
PC10: U7.64(PC10)
PC11: U7.1(PC11)
PC12: U7.2(PC12)
PC13: SB20.1 U7.3(PC13)
PC14: R31.1 U7.4(PC14-OSC32_IN)
PC15: R32.1 U7.5(PC15-OSC32_OUT)
PD0: U7.50(PD0)
PD1: U7.51(PD1)
PD2: U7.52(PD2)
PD3: U7.53(PD3)
PD4: U7.54(PD4)
PD5: U7.55(PD5)
PD6: U7.56(PD6)
PD8: SB30.1 U7.40(PD8)
PD9: SB29.1 U7.41(PD9)
PF0: R33.1 U7.10(PF0-OSC_IN) ; port MCO  [project net MCO]
PF1: R34.1 U7.11(PF1-OSC_OUT)
PF2: B2.3 B2.4 C28.2 U7.12(PF2-NRST) ; port NRST  [project net NRST]
NetB1_3: B1.3 B1.4 C16.2 R29.1 SB20.2
NetC16_1: C16.1 R26.2
NetC23_2: C23.2 R31.2 X2.2(X2)
NetC24_2: C24.2 R32.2 X2.1(X1)
NetC25_2: C25.2 R33.2 X3.2(X2)
NetC26_2: C26.2 R34.2 X3.1(X1)

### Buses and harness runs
bus PA[0..15] = port PA[0..15]
bus PB[0..15] = port PB[0..15]
bus PC[0..15] = port PC[0..15]
bus PD[0..9] = port PD[0..9]
bus PF[0..2] = port PF[0..2]

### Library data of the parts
B1 = MCD-00002: Non-Open Push-Button 0.1A 24V; Part_Type: Misc; Manufacturer_Part_Number: TD-0341; Manufacturer: WEALTHMETAL; Provided_By: SUBCO
B2 = MCD-00001: Non-Open Push-Button 0.1A 24V BLACK; Part_Type: Misc; Manufacturer_Part_Number: TD-0341; Manufacturer: WEALTHMETAL; Provided_By: SUBCO
C16 C28 = MCD-00211: as C1 on sheet ST_LINK_V2-1
C23 C24 = MCD-00650: Capacitor, MLCC, 6.8pF, 50V, NPO, -/+0.25pF, 0603, T=0,8mm; Part_Preference: Recommended; Manufacturer: YAGEO; Manufacturer_Part_Number: CC0603CRNPO9BN6R8
C25 C26 = MCD-00637: as C4 on sheet ST_LINK_V2-1
HW3 = MCD-01253: Yamaichi socket for LQFP64, with positioning pins.; Part_Type: Misc; Manufacturer_Part_Number: IC149-064-169-B5; Provided_By: SUBCO
HW10 = MCD-00634: Blue Hat for switch TD0341X-G01-BLU; Part_Type: Mechanical; Manufacturer_Part_Number: 988.16.09.3.00002_SH-517; Manufacturer: JIUBABA; Provided_By: SUBCO
HW11 = MCD-00635: Black Hat for switch TD0341X-G01-BLA; Part_Type: Mechanical; Manufacturer_Part_Number: 988.16.09.3.00003_SH-517; Manufacturer: JIUBABA; Provided_By: SUBCO
R26 R33 R34 = MCD-00224: as R13 on sheet ST_LINK_V2-1
R29 = MCD-00219: as R6 on sheet ST_LINK_V2-1
R31 R32 = MCD-00181: Resistor,0R,0603,ULO; Manufacturer_Part_Number: PMR03EZPJ000; Manufacturer: ROHM; ECCN_US: EAR99; ECCN_EU: NEC; Provided_By: SUBCO
SB20 = MCD-00071: as SB7 on sheet ST_LINK_V2-1
SB29 SB30 = MCD-00072: as SB6 on sheet ST_LINK_V2-1
U7 = MCD-00662: Medium-density performance line ARM-based 32-bit MCU with 128KB Flash. LQFP64 IC149-064-069-B5 socket footprint.; Part_Type: IC; Manufacturer: STMICROELECTRONICS; BMS_Part_Number: 9175318; ECCN_US: 3A991A2; ECCN_EU: NEC; Provided_By: SUBCO with ST control
X2 = MCD-00091: Crystal 32.768kHz, 6pF, +-20ppm, 50Kohms max, SMD; Part_Type: Crystal_Osc; Manufacturer_Part_Number: NX3215SA 32.768KHz EXS00A-MU00525; Manufacturer: NDK; BMS_Part_Number: 9157034; ECCN_US: EAR99; ECCN_EU: NEC; Provided_By: SUBCO
X3 = MCD-00092: as X1 on sheet ST_LINK_V2-1

## Sheet Power.SchDoc: Power
size A4; CompanyName: STMicroelectronics; Organization: Microcontrollers Division; SheetNumber: 6; SheetTotal: 8
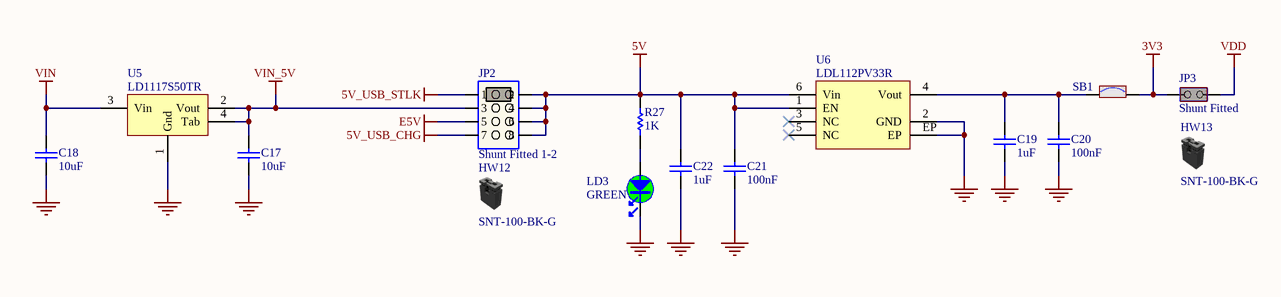
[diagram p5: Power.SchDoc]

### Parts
C17  value 10uF  [C0805]  (hidden comment: Capacitor)
C18  value 10uF  [C0805]  (hidden comment: Capacitor)
C19  value 1uF  [C0603]  (hidden comment: Capacitor)
C20  value 100nF  [C0603]  (hidden comment: Capacitor)
C21  value 100nF  [C0603]  (hidden comment: Capacitor)
C22  value 1uF  [C0603]  (hidden comment: Capacitor)
HW12  value SNT-100-BK-G  (hidden comment: Shunt Black 2.54mm)  (mechanical)
HW13  value SNT-100-BK-G  (hidden comment: Shunt Black 2.54mm)  (mechanical)
JP2  value Shunt Fitted 1-2  [CON_SAMTEC_TSW-104-07-X-D]  (hidden comment: Jumper_Header 4x2 Fitted 1-2)
JP3  value Shunt Fitted  [CON_SAMTEC_TSW-102-07-G-S]  (hidden comment: Jumper_Header 2x1 Fitted)
LD3  value GREEN  [LED_0603_GREEN]  (hidden comment: LED_green)
R27  value 1K  [R0603]  (hidden comment: Resistor)
SB1  SB_ON  [SOLDER-BRIDGE_R0603-0R]  (value not drawn)
U5  LD1117S50TR  [REG_SOT223-TAB]
U6  LDL112PV33R  [ICC_DFN6-EPAD_3X3_P095]

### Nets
3V3: JP3.2(NO) SB1.2
5V: C21.2 C22.2 JP2.2 JP2.4 JP2.6 JP2.8 R27.1 U6.1(EN) U6.6(Vin)
5V_USB_CHG: JP2.7
5V_USB_STLK: JP2.1
E5V: JP2.5
GND: C17.1 C18.1 C19.1 C20.1 C21.1 C22.1 LD3.2 U5.1(Gnd) U6.2(GND) U6.EP
VDD: JP3.1(COMMON)
VIN: C18.2 U5.3(Vin)
VIN_5V: C17.2 JP2.3 U5.2(Vout) U5.4(Tab)
NetC19_2: C19.2 C20.2 SB1.1 U6.4(Vout)
NetLD3_1: LD3.1 R27.2

Not connected (* = marked no-connect by the designer): U6 3(NC)* 5(NC)*

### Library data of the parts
C17 C18 = MCD-00014: Capacitor, MLCC, 10uF, 25V, X5R, 10%, 0805, T=0,85mm; Manufacturer_Part_Number: CC0805KRX5R8BB106; Manufacturer: YAGEO; ECCN_US: EAR99; ECCN_EU: NEC; Provided_By: SUBCO
C19 C22 = MCD-00010: as C7 on sheet ST_LINK_V2-1
C20 C21 = MCD-00211: as C1 on sheet ST_LINK_V2-1
HW12 HW13 = MCD-00043: as HW6 on sheet ST_LINK_V2-1
JP2 = MCD-00686: Header, 4x2, 2,54mm, VR, TH, Height 5.84mm/2.54mm - Shunt Fitted 1-2; Part_Type: Connector; Manufacturer_Part_Number: TSW-104-07-x-D; Manufacturer: SAMTEC; Provided_By: SUBCO
JP3 = MCD-00683: as JP4 on sheet ST_LINK_V2-1
LD3 = MCD-00050: as LD4 on sheet Arduino_extension_connectors
R27 = MCD-00070: as R18 on sheet ST_LINK_V2-1
SB1 = MCD-00071: as SB7 on sheet ST_LINK_V2-1
U5 = MCD-00088: IC REG LDO 5V 0.8A SOT223; Manufacturer: STMICROELECTRONICS; BMS_Part_Number: 9176133; ECCN_US: EAR99; ECCN_EU: NEC; Provided_By: SUBCO with ST control
U6 = MCD-00664: 1.2 A low quiescent current LDO with reverse current protection; Part_Type: IC; Manufacturer: STMICROELECTRONICS; BMS_Part_Number: 9176253; ECCN_US: EAR99; ECCN_EU: NEC; Provided_By: SUBCO with ST control

## Sheet STM32_microcontroller_power.SchDoc: STM32_microcontroller_power
size A4; SheetNumber: 4; SheetTotal: 8
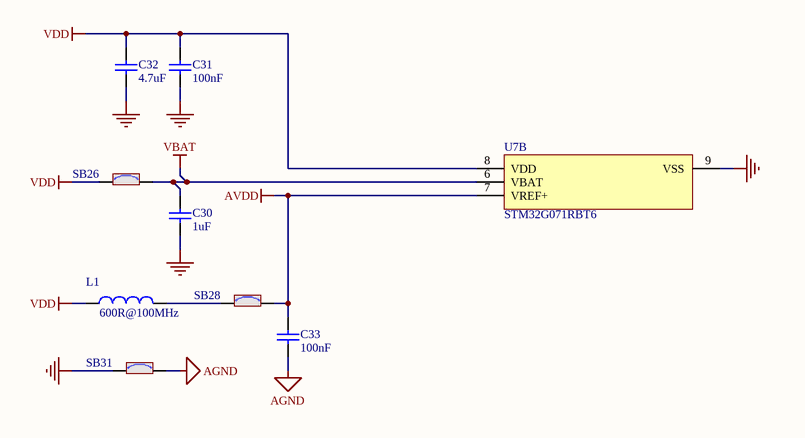
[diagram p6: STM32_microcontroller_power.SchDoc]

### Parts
C30  value 1uF  [C0603]  (hidden comment: Capacitor)
C31  value 100nF  [C0603]  (hidden comment: Capacitor)
C32  value 4.7uF  [C0603]  (hidden comment: Capacitor)
C33  value 100nF  [C0603]  (hidden comment: Capacitor)
L1  value 600R@100MHz  [L0603]  (hidden comment: BEAD)
SB26  SB_ON  [SOLDER-BRIDGE_R0603-0R]  (value not drawn)
SB28  SB_ON  [SOLDER-BRIDGE_R0603-0R]  (value not drawn)
SB31  SB_ON  [SOLDER-BRIDGE_R0603-0R]  (value not drawn)
U7  STM32G071RBT6  [ICC_LQFP64_10X10_P050_SOCKET_YAMAICHI_IC149-064-069-B5]  (part B of 2)

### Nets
AGND: C33.1 SB31.2
AVDD: C33.2 SB28.2 U7.7(VREF+)
GND: C30.1 C31.1 C32.1 SB31.1 U7.9(VSS)
VBAT: C30.2 SB26.2 U7.6(VBAT)
VDD: C31.2 C32.2 L1.1 SB26.1 U7.8(VDD)
NetL1_2: L1.2 SB28.1

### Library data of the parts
C30 = MCD-00010: as C7 on sheet ST_LINK_V2-1
C31 C33 = MCD-00211: as C1 on sheet ST_LINK_V2-1
C32 = MCD-00009: Capacitor, MLCC, 4.7uF, 16V, X5R, 10%, 0603, T=0.8mm; Manufacturer_Part_Number: CC0603KRX5R7BB475; Manufacturer: YAGEO; ECCN_US: EAR99; ECCN_EU: NEC; Provided_By: SUBCO
L1 = MCD-00047: SMD Chip ferrite bead, 600R@100MHz +/-25%, 350mA, 500mohm DC, 0603, T=0.8mm; Manufacturer_Part_Number: FCM1608KF-601T03; Manufacturer: TAI-TECH; Part_Type: Inductor; Provided_By: SUBCO
SB26 SB28 SB31 = MCD-00071: as SB7 on sheet ST_LINK_V2-1
U7 = MCD-00662: as U7 on sheet STM32_microcontroller_IOs

## Sheet HW_Mechanical_Parts.SchDoc: HW Mechanical parts
size A4; SheetNumber: 8; SheetTotal: 8
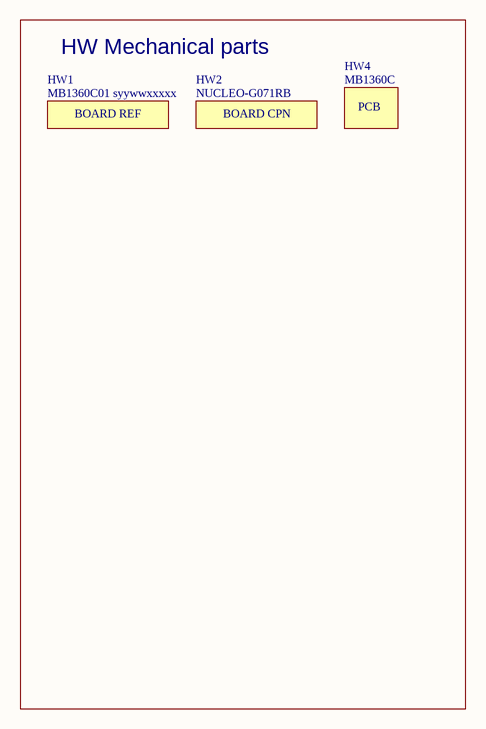
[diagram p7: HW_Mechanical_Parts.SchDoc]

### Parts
HW1  value MB1360C01 syywwxxxxx  [STICKER_25X9]  (hidden comment: STICKER_BOARD_REF)  (no BOM)
HW2  value NUCLEO-G071RB  (hidden comment: STICKER_BOARD_CPN)  (mechanical)
HW4  value MB1360C  (hidden comment: PCB)  (mechanical)

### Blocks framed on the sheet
HW Mechanical parts: HW1 HW2 HW4

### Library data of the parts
HW1 = MCD-00235: Sticker to mention board reference + serial number; Part_Type: Mechanical; Provided_By: SUBCO
HW2 = MCD-00549: Sticker to mention board CPN code; Part_Type: Mechanical; Provided_By: Subcon; Initial_Board_Reference: mb1319
HW4 = MCD-00216: PCB, xxxx for PCB number, Y for PCB revision; Part_Type: Mechanical; Provided_By: SUBCO

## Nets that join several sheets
3V3: ST_LINK_V2-1 (R22.1), Arduino_extension_connectors (5 pins), Power (JP3.2 SB1.2)
5V: ST_LINK_V2-1 (D2.1), Arduino_extension_connectors (CN6.5 CN7.18), Power (9 pins)
5V_USB_CHG: ST_LINK_V2-1 (10 pins), Arduino_extension_connectors (CN10.8), Power (JP2.7)
5V_USB_STLK: ST_LINK_V2-1 (C9.2 U4.1), Power (JP2.1)
AGND: Arduino_extension_connectors (C29.1 CN5.7 CN10.9 CN10.32), STM32_microcontroller_power (C33.1 SB31.2)
AVDD: Arduino_extension_connectors (C29.2 SB21.2), STM32_microcontroller_power (C33.2 SB28.2 U7.7)
E5V: ST_LINK_V2-1 (D5.1), Arduino_extension_connectors (CN7.6), Power (JP2.5)
GND: ST_LINK_V2-1 (47 pins), Arduino_extension_connectors (9 pins), STM32_microcontroller_IOs (11 pins), Power (10 pins), STM32_microcontroller_power (5 pins)
VBAT: Arduino_extension_connectors (CN7.33), STM32_microcontroller_power (C30.2 SB26.2 U7.6)
VDD: Arduino_extension_connectors (CN7.5), STM32_microcontroller_IOs (R29.2 SB29.2), Power (JP3.1), STM32_microcontroller_power (5 pins)
VIN: Arduino_extension_connectors (CN6.8 CN7.24), Power (C18.2 U5.3)
VIN_5V: ST_LINK_V2-1 (D4.1), Arduino_extension_connectors (R30.1), Power (C17.2 JP2.3 U5.2 U5.4)
MCO: ST_LINK_V2-1 (SB17.2), Arduino_extension_connectors (SB25.1), STM32_microcontroller_IOs (R33.1 U7.10)
NRST: ST_LINK_V2-1 (SB19.2), Arduino_extension_connectors (CN6.3 CN7.14), STM32_microcontroller_IOs (B2.3 B2.4 C28.2 U7.12)
PA0: Arduino_extension_connectors (CN7.28 CN8.1), STM32_microcontroller_IOs (U7.17)
PA1: Arduino_extension_connectors (CN7.30 CN8.2), STM32_microcontroller_IOs (U7.18)
PA2: Arduino_extension_connectors (CN10.34), STM32_microcontroller_IOs (U7.19)
PA3: Arduino_extension_connectors (CN10.6), STM32_microcontroller_IOs (U7.20)
PA4: Arduino_extension_connectors (CN7.32 CN8.3), STM32_microcontroller_IOs (U7.21)
PA5: Arduino_extension_connectors (CN5.6 CN10.11 SB22.2), STM32_microcontroller_IOs (U7.22)
PA6: Arduino_extension_connectors (CN5.5 CN10.13), STM32_microcontroller_IOs (U7.23)
PA7: Arduino_extension_connectors (CN5.4 CN10.15), STM32_microcontroller_IOs (U7.24)
PA8: Arduino_extension_connectors (CN9.8 CN10.23), STM32_microcontroller_IOs (U7.36)
PA9: Arduino_extension_connectors (CN5.1 CN10.21), STM32_microcontroller_IOs (U7.37)
PA10: Arduino_extension_connectors (CN9.3 CN10.33), STM32_microcontroller_IOs (U7.42)
PA11: Arduino_extension_connectors (CN10.14), STM32_microcontroller_IOs (U7.43)
PA12: Arduino_extension_connectors (CN10.12), STM32_microcontroller_IOs (U7.44)
PA13: ST_LINK_V2-1 (SB13.1), Arduino_extension_connectors (CN7.13), STM32_microcontroller_IOs (U7.45)
PA14: ST_LINK_V2-1 (SB9.1), Arduino_extension_connectors (CN7.7), STM32_microcontroller_IOs (U7.46)
PA15: Arduino_extension_connectors (CN7.17), STM32_microcontroller_IOs (U7.47)
PB0: Arduino_extension_connectors (CN5.3 CN10.17), STM32_microcontroller_IOs (U7.27)
PB1: Arduino_extension_connectors (CN7.34 CN8.4), STM32_microcontroller_IOs (U7.28)
PB2: Arduino_extension_connectors (CN10.22), STM32_microcontroller_IOs (U7.29)
PB3: Arduino_extension_connectors (CN9.4 CN10.31), STM32_microcontroller_IOs (U7.57)
PB4: Arduino_extension_connectors (CN9.6 CN10.27), STM32_microcontroller_IOs (U7.58)
PB5: Arduino_extension_connectors (CN9.5 CN10.29), STM32_microcontroller_IOs (U7.59)
PB6: Arduino_extension_connectors (CN10.24), STM32_microcontroller_IOs (U7.60)
PB7: Arduino_extension_connectors (CN7.21), STM32_microcontroller_IOs (U7.61)
PB8: Arduino_extension_connectors (CN5.10 CN10.3 SB5.2), STM32_microcontroller_IOs (U7.62)
PB9: Arduino_extension_connectors (CN5.9 CN10.5 SB2.2), STM32_microcontroller_IOs (U7.63)
PB10: Arduino_extension_connectors (CN10.28), STM32_microcontroller_IOs (U7.30)
PB11: Arduino_extension_connectors (SB4.1), STM32_microcontroller_IOs (U7.31)
PB12: Arduino_extension_connectors (SB3.1), STM32_microcontroller_IOs (U7.32)
PB13: Arduino_extension_connectors (CN10.30), STM32_microcontroller_IOs (U7.33)
PB14: Arduino_extension_connectors (CN9.7 CN10.25), STM32_microcontroller_IOs (U7.34)
PB15: Arduino_extension_connectors (CN10.26), STM32_microcontroller_IOs (U7.35)
PC0: Arduino_extension_connectors (CN10.18), STM32_microcontroller_IOs (U7.13)
PC1: Arduino_extension_connectors (CN10.16), STM32_microcontroller_IOs (U7.14)
PC2: Arduino_extension_connectors (CN7.35), STM32_microcontroller_IOs (U7.15)
PC3: Arduino_extension_connectors (CN7.37), STM32_microcontroller_IOs (U7.16)
PC4: Arduino_extension_connectors (CN9.2 CN10.35), STM32_microcontroller_IOs (U7.25)
PC5: Arduino_extension_connectors (CN9.1 CN10.37), STM32_microcontroller_IOs (U7.26)
PC6: Arduino_extension_connectors (CN10.4), STM32_microcontroller_IOs (U7.38)
PC7: Arduino_extension_connectors (CN5.2 CN10.19), STM32_microcontroller_IOs (U7.39)
PC8: Arduino_extension_connectors (CN10.2), STM32_microcontroller_IOs (U7.48)
PC9: Arduino_extension_connectors (CN10.1), STM32_microcontroller_IOs (U7.49)
PC10: Arduino_extension_connectors (CN7.1), STM32_microcontroller_IOs (U7.64)
PC11: Arduino_extension_connectors (CN7.2), STM32_microcontroller_IOs (U7.1)
PC12: Arduino_extension_connectors (CN7.3), STM32_microcontroller_IOs (U7.2)
PC13: Arduino_extension_connectors (CN7.23), STM32_microcontroller_IOs (SB20.1 U7.3)
PC14: Arduino_extension_connectors (SB23.1), STM32_microcontroller_IOs (R31.1 U7.4)
PC15: Arduino_extension_connectors (SB24.1), STM32_microcontroller_IOs (R32.1 U7.5)
PD0: Arduino_extension_connectors (CN7.9), STM32_microcontroller_IOs (U7.50)
PD1: Arduino_extension_connectors (CN7.10), STM32_microcontroller_IOs (U7.51)
PD2: Arduino_extension_connectors (CN7.4), STM32_microcontroller_IOs (U7.52)
PD3: Arduino_extension_connectors (CN7.11), STM32_microcontroller_IOs (U7.53)
PD4: Arduino_extension_connectors (CN7.15), STM32_microcontroller_IOs (U7.54)
PD5: Arduino_extension_connectors (CN7.26), STM32_microcontroller_IOs (U7.55)
PD6: Arduino_extension_connectors (CN10.10), STM32_microcontroller_IOs (U7.56)
PD8: Arduino_extension_connectors (CN10.36), STM32_microcontroller_IOs (SB30.1 U7.40)
PD9: Arduino_extension_connectors (CN10.38), STM32_microcontroller_IOs (SB29.1 U7.41)
PF1: Arduino_extension_connectors (SB27.1), STM32_microcontroller_IOs (R34.1 U7.11)

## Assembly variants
MB1360-B01: not fitted C11 C25 C26 C29 HW3 R2 R3 R33 R34 X3
G071RB: not fitted C11 C25 C26 C29 HW3 R2 R3 R33 R34 X3
G070RB: not fitted C11 C25 C26 C29 HW3 R2 R3 R33 R34 X3
G0B1RE: not fitted C11 C25 C26 C29 HW3 R2 R3 R33 R34 X3
G071RB_S: not fitted C11 C25 C26 C29 R2 R3 R33 R34 X3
